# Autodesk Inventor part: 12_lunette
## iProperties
Shininess: 20.0
Length Units: 11270
Angle Units: 11279
Time Units: 11290
Mass Units: 11283
Length Display Precision: 3
Angle Display Precision: 2
Created: 2000-10
Part Number: 12_lunette
Material: Par défaut
Document SubType Name: Modélisation
Density: 0.0
Volumn: 0.0
Area: 0.0
PropertySet Name: Model Information
Control State: 0
Master: False
Checked Out: False
Author: Laurent GAUTHERON
